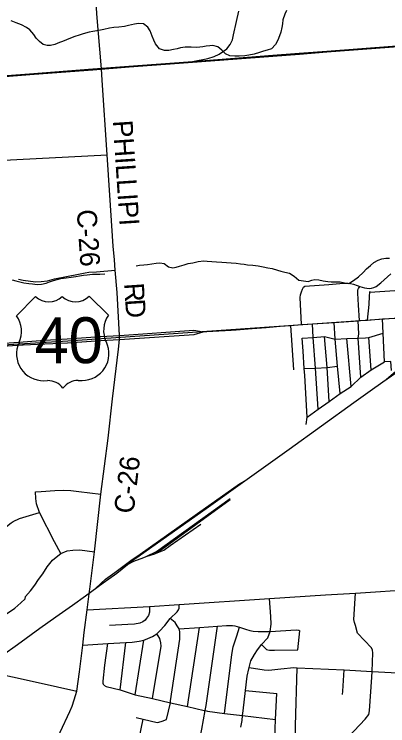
# Model space of a CAD drawing. Extents: x 114843 to 284848, y 317643 to 566895.
# Drawn here: x 173593 to 179255, y 377735 to 388525 of the extents above; entities that cross this region are included whole.
import ezdxf

# ---------------------------------------------------------------- set-up
doc = ezdxf.new("R2010")
doc.units = 0
for name, color, linetype in [('GM_X_City_Street', 7, 'Continuous'), ('GM_X_County_Road', 7, 'Continuous'), ('GM_X_County_Road_Text', 7, 'Continuous'), ('GM_X_Minor_River', 7, 'Continuous'), ('GM_X_Rail_Line', 7, 'Continuous'), ('GM_X_Township_Road', 7, 'Continuous'), ('GM_X_US_Location', 7, 'Continuous'), ('GM_X_US_Route', 7, 'Continuous'), ('GM_X_US_Shield', 7, 'Continuous')]:
    doc.layers.add(name, color=color, linetype=linetype)

msp = doc.modelspace()

# ---------------------------------------------------------------- linework, layer by layer
at = {"layer": 'GM_X_City_Street'}
for p, q in [((178985, 384312), (179652, 384356)), ((177782, 383807), (177828, 383135)), ((176220, 378025), (176399, 379224)), ((177891, 378888), (177923, 379175)), ((175199, 378278), (175285, 379000)), ((175425, 378206), (175560, 379035)), ((178574, 378262), (178594, 378582)), ((177099, 378270), (177574, 378222)), ((178571, 378208), (178574, 378262))]:
    msp.add_line(p, q, dxfattribs=at)
for points in [[(177948, 383818), (177927, 384232), (177935, 384272), (177946, 384316), (177963, 384357), (177979, 384384), (177998, 384400), (178360, 384429), (178530, 384440), (178616, 384446), (178657, 384447), (178690, 384443), (178734, 384430), (178791, 384412), (178830, 384397), (178903, 384376), (178937, 384369), (178972, 384367), (179008, 384371), (179043, 384380), (179079, 384394), (179152, 384453), (179303, 384590)], [(178826, 383880), (178810, 384113), (178802, 384297), (178804, 384344), (178812, 384366), (178830, 384397)], [(178950, 383888), (178973, 384123), (178981, 384249), (178985, 384312), (178988, 384325)], [(177463, 379663), (178314, 379718), (178766, 379744), (179671, 379808), (179956, 379828), (180655, 379873), (180696, 379876)], [(178662, 377565), (178913, 377835), (178966, 377906), (178981, 377963), (179014, 378471), (179018, 378560), (179031, 378843), (179026, 378879), (179008, 378915), (178798, 379141), (178766, 379254), (178750, 379300), (178743, 379346), (178766, 379744)], [(174701, 379493), (175645, 379546), (176092, 379574), (177463, 379663)], [(177283, 378888), (177286, 378892), (177339, 378969), (177437, 379067), (177471, 379165), (177487, 379276), (177482, 379390), (177463, 379663)], [(174633, 378959), (175010, 378984), (175285, 379000), (175382, 379005), (175487, 379018), (175560, 379035), (175616, 379057), (175688, 379090), (175756, 379131), (175795, 379167), (175878, 379256), (175959, 379359), (176061, 379465), (176085, 379491), (176093, 379519), (176092, 379574)], [(175645, 379546), (175644, 379459), (175626, 379409), (175600, 379365), (175576, 379336), (175541, 379309), (175495, 379289), (175417, 379277), (175315, 379269), (175036, 379253)], [(175901, 377830), (175961, 378084), (175963, 378112), (176105, 379046), (176105, 379157), (176095, 379205), (176065, 379252), (176032, 379299), (175959, 379359)], [(176095, 379205), (176399, 379224), (176675, 379244), (176813, 379254), (176859, 379257), (176900, 379255), (176937, 379248), (176973, 379240), (177009, 379230), (177097, 379200), (177163, 379181), (177217, 379171), (177293, 379162), (177471, 379165), (177868, 379190), (177908, 379183), (177923, 379175)], [(176350, 377121), (176342, 377141), (176339, 377175), (176352, 377265), (176383, 377414), (176412, 377555), (176436, 377681), (176488, 377964), (176505, 378043), (176675, 379244)], [(176778, 377920), (176891, 378816), (176912, 378934), (176943, 379025), (176965, 379099), (177009, 379230)], [(175689, 378146), (175822, 378941), (175817, 378993), (175799, 379057), (175777, 379098), (175756, 379131)], [(174951, 378350), (174943, 378376), (174943, 378410), (174968, 378656), (175010, 378984)], [(177154, 378620), (177179, 378722), (177233, 378817), (177283, 378888)], [(177339, 378969), (177418, 378893), (177438, 378888), (177464, 378880), (177540, 378879), (177891, 378888)], [(172785, 378651), (173956, 378390), (174542, 378262)], [(177027, 377715), (177048, 377813), (177055, 377888), (177062, 377962), (177099, 378270), (177125, 378487), (177150, 378599), (177154, 378620)], [(177154, 378620), (177384, 378583), (177450, 378580), (177634, 378597), (177829, 378619), (177883, 378612), (178594, 378582), (179018, 378560), (179404, 378540), (179724, 378523), (180009, 378512), (180330, 378501), (180632, 378491), (180937, 378474)], [(178183, 376601), (178195, 376803), (178191, 376837), (178172, 376867), (177840, 376965), (177774, 376986), (177737, 377017), (177704, 377063), (177686, 377117), (177685, 377169), (177714, 377230), (177779, 377335), (177808, 377381), (177843, 377437), (177855, 377487), (177859, 377734), (177883, 378612)], [(174951, 378350), (174985, 378328), (175199, 378278), (175425, 378206), (175689, 378146), (175961, 378084), (176220, 378025), (176470, 377968), (176488, 377964), (176525, 377955), (176778, 377920), (177055, 377888), (177555, 377829)], [(177191, 375618), (177232, 375689), (177242, 375731), (177286, 376186), (177329, 376635), (177352, 376871), (177382, 377181), (177389, 377256), (177410, 377322), (177474, 377488), (177480, 377504), (177538, 377601), (177550, 377634), (177549, 377690), (177555, 377829), (177574, 378222)], [(175443, 377859), (175546, 377835), (175761, 377784), (175785, 377788), (175833, 377805), (175901, 377830)], [(175465, 377414), (175489, 377540), (175546, 377835)]]:
    msp.add_lwpolyline(points, dxfattribs=at)
at = {"layer": 'GM_X_County_Road'}
for points in [[(174928, 387527), (174916, 387697), (174846, 388529), (174802, 389432)], [(175111, 384803), (175094, 385009), (175044, 385783), (175003, 386393), (174928, 387527)], [(175191, 383593), (175188, 383654), (175151, 384305), (175124, 384644), (175111, 384803)], [(174907, 381249), (175015, 382097), (175084, 382694), (175173, 383447), (175191, 383593)], [(174738, 379806), (174810, 380374), (174907, 381249)], [(174701, 379493), (174734, 379775), (174738, 379806)], [(173710, 376226), (173769, 376421), (173808, 376535), (173908, 376772), (174092, 377186), (174226, 377498), (174288, 377639), (174435, 377949), (174469, 378034), (174502, 378130), (174542, 378262), (174583, 378555), (174633, 378959), (174654, 379149), (174701, 379493)]]:
    msp.add_lwpolyline(points, dxfattribs=at)
at = {"layer": 'GM_X_Minor_River'}
for points in [[(177722, 388582), (177693, 388524), (177667, 388442), (177659, 388378), (177652, 388324), (177632, 388252), (177613, 388200), (177587, 388134), (177552, 388066), (177492, 388000), (177426, 387978), (177374, 387965), (177312, 387947), (177229, 387920), (177149, 387904), (177087, 387894), (177005, 387889), (176937, 387887), (176861, 387894), (176797, 387926), (176738, 387983), (176680, 388029), (176606, 388050), (176556, 388048), (176504, 388040), (176454, 388033), (176360, 388019), (176274, 388026), (176186, 388026), (176115, 388017), (176063, 388003), (176009, 387989), (175937, 387976), (175873, 387974), (175795, 388003)], [(175795, 388003), (175734, 388075), (175708, 388132), (175684, 388194), (175655, 388272), (175619, 388327), (175555, 388379), (175479, 388386), (175417, 388374), (175327, 388355), (175263, 388339), (175181, 388329), (175103, 388322), (175037, 388312), (174949, 388295), (174899, 388285), (174844, 388275), (174786, 388264), (174730, 388252), (174638, 388227), (174576, 388209), (174512, 388187), (174444, 388160), (174385, 388136), (174327, 388114), (174277, 388095), (174209, 388067), (174143, 388049), (174091, 388050), (174031, 388068), (173975, 388111), (173927, 388161), (173888, 388217), (173830, 388290), (173778, 388326), (173704, 388365), (173623, 388397), (173547, 388426)], [(175442, 384710), (175492, 384719), (175558, 384723), (175612, 384729), (175680, 384738), (175744, 384752), (175798, 384753), (175866, 384745), (175934, 384696), (175996, 384678), (176046, 384688), (176100, 384705), (176170, 384725), (176231, 384743), (176299, 384756), (176381, 384776), (176465, 384787), (176517, 384783), (176587, 384774), (176659, 384770), (176741, 384763), (176811, 384759), (176879, 384755), (176957, 384750), (177023, 384742), (177079, 384735), (177131, 384727), (177209, 384718), (177289, 384708), (177369, 384695), (177437, 384681), (177501, 384668), (177583, 384644), (177635, 384627), (177695, 384613), (177766, 384597), (177838, 384552), (177908, 384493), (177980, 384483), (178048, 384470), (178102, 384490), (178152, 384504), (178212, 384497), (178278, 384483), (178346, 384471), (178398, 384468), (178474, 384466), (178532, 384465), (178598, 384453), (178664, 384442), (178734, 384486), (178811, 384544), (178883, 384607), (178933, 384663), (178992, 384715), (179042, 384761), (179108, 384798), (179165, 384816), (179227, 384824), (179283, 384825)], [(173560, 384499), (173618, 384483), (173680, 384468), (173738, 384454), (173814, 384441), (173869, 384435), (173941, 384426), (174004, 384432), (174076, 384448), (174130, 384465), (174186, 384487), (174244, 384505), (174300, 384518), (174378, 384528), (174458, 384537), (174525, 384549), (174581, 384557), (174643, 384566), (174701, 384574), (174781, 384581), (174893, 384585), (174967, 384588)]]:
    msp.add_lwpolyline(points, dxfattribs=at)
at = {"layer": 'GM_X_Rail_Line'}
msp.add_line((175594, 380300), (175722, 380342), dxfattribs=at)
for points in [[(176295, 387809), (176527, 387856), (176622, 387884), (176701, 387918), (176816, 388000), (176864, 388064), (176901, 388135), (176919, 388214), (176962, 388416), (176997, 388570)], [(170721, 387385), (170774, 387389), (170947, 387403), (171095, 387417), (171130, 387418), (171245, 387426), (172741, 387541), (173133, 387569), (173826, 387624), (174782, 387696), (175332, 387739), (176228, 387804), (177511, 387903), (177914, 387933), (178331, 387967), (182044, 388248)], [(171403, 387425), (172742, 387528), (173134, 387556), (173827, 387611), (174783, 387683), (175333, 387726), (176229, 387791), (177512, 387890), (177915, 387920), (178332, 387954), (182045, 388235)], [(139976, 381530), (141702, 381687), (142931, 381777), (145059, 381883), (151606, 382247), (160057, 382729), (166950, 383110), (174406, 383574), (180366, 383985)], [(179236, 382990), (179379, 383114), (179980, 383558)], [(171398, 377356), (172096, 377857), (172494, 378142), (172797, 378359), (173218, 378663), (173414, 378803), (173640, 378965), (173983, 379213), (174225, 379386), (174476, 379566), (174672, 379706), (174940, 379901), (175146, 380047), (175389, 380244), (175466, 380298), (175508, 380328), (176501, 381029), (177126, 381476), (177266, 381576), (177760, 381932), (178739, 382636), (178988, 382815), (179181, 382953), (179526, 383187)], [(174829, 379820), (174976, 379960), (175118, 380059), (175382, 380254), (175459, 380308), (175501, 380338), (176493, 381040), (177006, 381405), (177087, 381448)], [(175594, 380300), (175749, 380378), (176867, 381179)], [(176867, 381161), (175823, 380401), (175722, 380342)], [(175722, 380342), (175736, 380346), (175860, 380397), (175959, 380471), (176422, 380793)], [(175310, 380179), (175408, 380233), (175560, 380289), (175594, 380300)]]:
    msp.add_lwpolyline(points, dxfattribs=at)
at = {"layer": 'GM_X_Township_Road'}
for p, q in [((173288, 386305), (175003, 386393)), ((177971, 383415), (177957, 383612)), ((179002, 383133), (178969, 383622)), ((178701, 382881), (178634, 383607)), ((178034, 382416), (178202, 382534))]:
    msp.add_line(p, q, dxfattribs=at)
for points in [[(173659, 384506), (173727, 384492), (173914, 384465), (174001, 384470), (174097, 384482), (174204, 384514), (174568, 384582), (174666, 384604), (174724, 384612), (174839, 384618), (175124, 384644)], [(178202, 382534), (178159, 383157), (178124, 383625), (178114, 383829)], [(178536, 382772), (178491, 383188), (178459, 383600), (178443, 383852)], [(178848, 383023), (178809, 383615), (178818, 383678), (178805, 383878)], [(179207, 383256), (179188, 383691), (179175, 383906)], [(177957, 383612), (178124, 383625), (178298, 383638), (178459, 383600), (178634, 383607), (178809, 383615), (178916, 383619)], [(178367, 382650), (178336, 383168), (178298, 383638)], [(178916, 383619), (178969, 383622), (179188, 383691)], [(177996, 383046), (177990, 383151), (177971, 383415)], [(177990, 383151), (178159, 383157), (178336, 383168), (178491, 383188)], [(178202, 382534), (178367, 382650), (178536, 382772), (178701, 382881), (178848, 383023), (179002, 383133), (179207, 383256)], [(179314, 383125), (179301, 383261), (179207, 383256)], [(178018, 382303), (178034, 382416), (177996, 383046)], [(173913, 381282), (173999, 381290), (174209, 381301), (174346, 381309), (174452, 381302), (174573, 381286), (174907, 381249)], [(174301, 380345), (174202, 380523), (173975, 380971), (173929, 381100), (173919, 381180), (173913, 381282)], [(172781, 379997), (172792, 380008), (173471, 380750), (173503, 380775), (173547, 380811), (173575, 380831), (173673, 380879), (173823, 380925), (173975, 380971)], [(173476, 379434), (173601, 379519), (173695, 379597), (173761, 379660), (173766, 379694), (173838, 379782), (173904, 379869), (173962, 379953), (174028, 380041), (174094, 380146), (174172, 380246), (174230, 380290), (174301, 380345), (174394, 380387), (174483, 380400), (174589, 380405), (174810, 380374)]]:
    msp.add_lwpolyline(points, dxfattribs=at)
at = {"layer": 'GM_X_US_Route'}
for p, q in [((176512, 383713), (176881, 383736)), ((176459, 383709), (176512, 383713)), ((173194, 383478), (173719, 383510))]:
    msp.add_line(p, q, dxfattribs=at)
for points in [[(177623, 383794), (177782, 383807), (177948, 383818), (178114, 383829), (178443, 383852), (178805, 383878), (178826, 383880), (178950, 383888), (179175, 383906), (179550, 383927), (179695, 383935)], [(173061, 383511), (173293, 383526), (173726, 383559), (174056, 383581), (174395, 383604), (174902, 383637), (175188, 383654), (176315, 383732), (176459, 383709)], [(176881, 383736), (176955, 383741), (177199, 383760)], [(177199, 383760), (177411, 383777), (177623, 383794)], [(175191, 383593), (176320, 383667), (176459, 383709)], [(173719, 383510), (173729, 383510), (174059, 383528), (174300, 383539)], [(174300, 383539), (174399, 383544), (174906, 383577), (175191, 383593)]]:
    msp.add_lwpolyline(points, dxfattribs=at)
at = {"layer": 'GM_X_US_Shield'}
for p, q in [((173916, 384244), (173628, 383952)), ((175020, 383962), (174728, 384250)), ((174041, 382968), (174099, 382969)), ((174563, 382972), (174621, 382973))]:
    msp.add_line(p, q, dxfattribs=at)
for centre, radius, start, end in [((174117, 384452), 290, 225.9857, 314.8397), ((174523, 384455), 290, 225.9857, 314.8397), ((173297, 383716), 406, 334.9598, 35.4136), ((175354, 383731), 406, 145.4118, 205.8656), ((174034, 383374), 406, 155.2446, 271.051), ((174623, 383379), 406, 269.7745, 25.5808), ((174101, 382679), 290, 37.2826, 90.4127), ((174565, 382682), 290, 90.4127, 143.5428)]:
    msp.add_arc(centre, radius, start, end, dxfattribs=at)

# ---------------------------------------------------------------- texts
at = {"layer": 'GM_X_County_Road_Text'}
for s, rotation, p in [('PHILLIPI', 273.7895, (175086, 386910)), ('C-26', 273.8491, (174540, 385557)), ('R', 273.8222, (175257, 384442)), ('D', 273.6901, (175274, 384198)), ('C-26', 83.2822, (175401, 380942))]:
    msp.add_text(s, height=300, rotation=rotation, dxfattribs=at).set_placement(p)
at = {"layer": 'GM_X_US_Location'}
for s, p in [('0', (174326, 383574)), ('/', (174326, 383574)), ('40', (174121, 383366))]:
    msp.add_text(s, height=1, rotation=0.4127, dxfattribs=at).set_placement(p)
at = {"layer": 'GM_X_US_Shield'}
msp.add_text('40', height=696.1, rotation=0.4127, dxfattribs=at).set_placement((173902, 383228))

doc.saveas('drawing.dxf')
